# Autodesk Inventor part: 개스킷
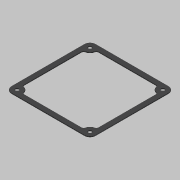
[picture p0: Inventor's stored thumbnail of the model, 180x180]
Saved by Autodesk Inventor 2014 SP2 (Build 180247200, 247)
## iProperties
Created: 2019-04
Part Number: 개스킷
Material: 고무
Document SubType Name: Modeling
Designer: mduedu
Density: 0.93 g/cm^3
Appearance: 고무 - 검은색 - 버전 1.1
Mass: 2.32152 g
Surface Area: 58.0824 cm^2
Volume: 2.49626 cm^3
Author: mduedu
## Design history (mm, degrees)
sketch "스케치1"
  geometry: L1 (52.5, 52.5)-(-52.5, 52.5); L2 (-52.5, 52.5)-(-52.5, -52.5); L3 (-52.5, -52.5)-(52.5, -52.5); L4 (52.5, -52.5)-(52.5, 52.5); L5 (52.5, 52.5)-(-52.5, -52.5); L6 (-52.5, 52.5)-(52.5, -52.5); 1 further point
  constraints: 12 end point, 2 midpoint, 2 parallel, 1 horizontal, 1 perpendicular
  dimensions: "d0" = 105 distance of L3.end L2.end; "d1" = 105 distance of L2.end L1.end
extrude "돌출1" new body sketch "스케치1" distance "d2" = 1; taper "d3" = 0 deg
sketch "스케치2"
  geometry: L1 (-52.5, -52.5)-(52.5, -52.5) reference; L2 (52.5, -52.5)-(52.5, 52.5) reference; L3 (52.5, 52.5)-(-52.5, 52.5) reference; L4 (-52.5, 52.5)-(-52.5, -52.5) reference; L5 (-46.5, 46.5)-(46.5, 46.5); L6 (46.5, 46.5)-(46.5, -46.5); L7 (46.5, -46.5)-(-46.5, -46.5); L8 (-46.5, -46.5)-(-46.5, 46.5); 1 further point
  constraints: 8 end point, 3 other
  dimensions: "d4" = 6 distance between parallel lines of L5 L3
extrude "돌출2" cut sketch "스케치2" stored distance "d5" = 1; taper "d6" = 0 deg
fillet "모깎기1" dims "d7" = 7
sketch "스케치3"
  geometry: A1 r 7 centre (-45.5, 45.5) between (-45.5, 52.5) and (-52.5, 45.5) reference; A2 r 7 centre (-45.5, -45.5) between (-52.5, -45.5) and (-45.5, -52.5) reference; A3 r 7 centre (45.5, -45.5) between (45.5, -52.5) and (52.5, -45.5) reference; A4 r 7 centre (45.5, 45.5) between (52.5, 45.5) and (45.5, 52.5) reference; 5 further points
  constraints: 4 coincident, 4 vertical alignment, 8 other
extrude "돌출3" join sketch "스케치3" stored distance "d8" = 1; taper "d9" = 0 deg
fillet "모깎기2" dims "d10" = 3
sketch "스케치4"
  geometry: A1 r 7 centre (-45.5, 45.5) between (-45.5, 52.5) and (-52.5, 45.5) reference; A2 r 7 centre (45.5, 45.5) between (52.5, 45.5) and (45.5, 52.5) reference; A3 r 7 centre (45.5, -45.5) between (45.5, -52.5) and (52.5, -45.5) reference; A4 r 7 centre (-45.5, -45.5) between (-52.5, -45.5) and (-45.5, -52.5) reference; 5 further points
  constraints: 4 coincident
hole "구멍1" sketch "스케치4" at (-45.5, 45.5), (45.5, 45.5), (45.5, -45.5), (-45.5, -45.5) diameter "d11" = 4.5; stored, may be unused: countersink angle "d15" = 90 deg, drill point angle "d17" = 118 deg; dims "d12" = 6, "d13" = 4, "d14" = 2, "d16" = 8
node "솔리드1"
node "투영된 루프1"
